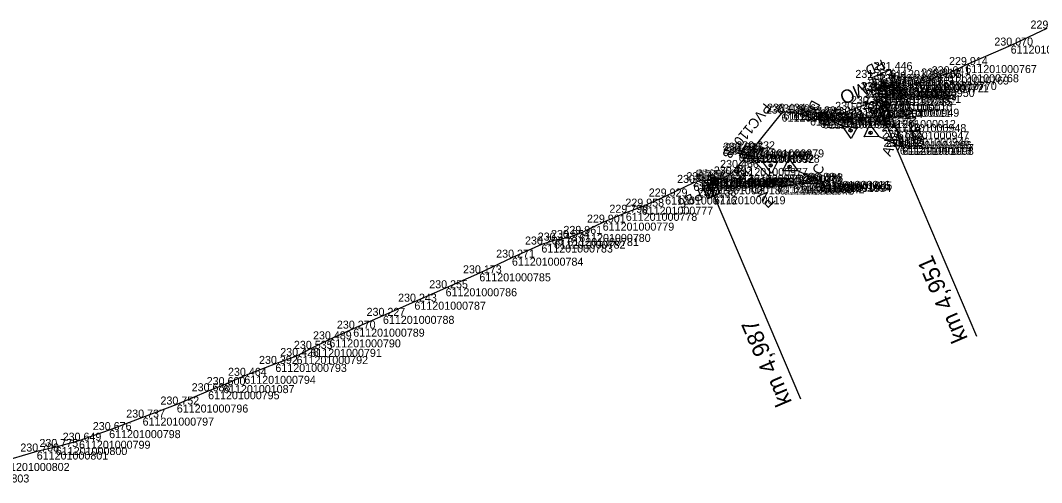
# Model space of a CAD drawing. Extents: x -771040 to -768909, y -1052366 to -1050115.
# Drawn here: x -770450.8 to -770297.8, y -1050286.7 to -1050217.5 of the extents above; entities that cross this region are included whole.
import ezdxf

# ---------------------------------------------------------------- set-up
doc = ezdxf.new("R2010")
doc.units = 0
for name, color, linetype in [('Vrstva 23', 7, 'Continuous'), ('Vrstva 27', 7, 'Continuous'), ('Vrstva 28', 7, 'Continuous'), ('Vrstva 3', 7, 'Continuous'), ('Vrstva 35', 7, 'Continuous'), ('Vrstva 4', 7, 'Continuous'), ('Vrstva 60', 7, 'Continuous'), ('Vrstva 61', 7, 'Continuous')]:
    doc.layers.add(name, color=color, linetype=linetype)

msp = doc.modelspace()

# ---------------------------------------------------------------- linework, layer by layer
at = {"layer": 'Vrstva 23'}
msp.add_lwpolyline([(-770322.43, -1050227.95), (-770319.66, -1050226.75), (-770320.47, -1050224.93), (-770323.23, -1050226.12), (-770322.43, -1050227.95)], dxfattribs=at)
at = {"layer": 'Vrstva 27'}
for p, q in [((-770321.21, -1050227.9), (-770321.22, -1050227.91)), ((-770321.89, -1050229.9), (-770321.85, -1050229.98)), ((-770347.21, -1050241.03), (-770347.17, -1050241.12))]:
    msp.add_line(p, q, dxfattribs=at)
msp.add_lwpolyline([(-770321.21, -1050227.91), (-770323.05, -1050228.7), (-770323.31, -1050228.09), (-770321.48, -1050227.3)], close=True, dxfattribs=at)
msp.add_lwpolyline([(-770321.56, -1050228.79), (-770322.13, -1050228.31), (-770322.17, -1050229.05)], dxfattribs=at)
for centre in [(-770321.87, -1050229.94), (-770347.19, -1050241.08)]:
    msp.add_circle(centre, 0.5, dxfattribs=at)
at = {"layer": 'Vrstva 28'}
for points in [[(-770296.98, -1050218.73), (-770302.4, -1050221.28), (-770309.19, -1050224.19), (-770311.88, -1050225.57), (-770313.36, -1050225.91), (-770315.2, -1050226.73), (-770316.4, -1050227.06), (-770317.15, -1050227.06), (-770318.51, -1050227.77)], [(-770321.45, -1050226.44), (-770322.26, -1050228)], [(-770321.21, -1050228.22), (-770321.27, -1050227.53), (-770321.45, -1050226.44)], [(-770321.21, -1050228.22), (-770321.23, -1050228.95), (-770321.77, -1050229.15)], [(-770320.55, -1050228.68), (-770321.21, -1050228.22)], [(-770318.51, -1050227.77), (-770320.55, -1050228.68)], [(-770321.77, -1050229.15), (-770323.89, -1050230.03), (-770326.25, -1050230.91)], [(-770321.77, -1050229.15), (-770321.87, -1050229.94)], [(-770320.55, -1050228.68), (-770321.23, -1050228.95)], [(-770318.95, -1050235.57), (-770319.23, -1050235.09), (-770319.31, -1050234.14), (-770319.76, -1050233.03), (-770320.82, -1050230.73), (-770321.23, -1050228.95)], [(-770341.08, -1050236.82), (-770336.74, -1050231.46), (-770336.46, -1050231.18)], [(-770336.46, -1050231.18), (-770334.95, -1050231.27), (-770332.47, -1050232.05), (-770330.96, -1050232.4)], [(-770326.25, -1050230.91), (-770327.95, -1050231.6), (-770330.56, -1050232.5)], [(-770321.33, -1050232.43), (-770322.07, -1050230.78), (-770321.87, -1050229.94)], [(-770330.96, -1050232.4), (-770331.13, -1050231.93), (-770331.05, -1050231.58), (-770330.67, -1050231.7)], [(-770330.96, -1050232.4), (-770330.56, -1050232.5)], [(-770318.95, -1050235.57), (-770318.63, -1050236.04), (-770318.64, -1050236.45), (-770319.01, -1050236.41)], [(-770345.53, -1050241.12), (-770344.45, -1050240.58), (-770343.5, -1050239.6), (-770341.74, -1050237.61), (-770341.08, -1050236.82)], [(-770342.55, -1050237.66), (-770343.17, -1050237.46), (-770343.05, -1050237.02), (-770342.73, -1050237.13)], [(-770342.55, -1050237.66), (-770341.74, -1050237.61)], [(-770333.74, -1050241.81), (-770335, -1050242.2), (-770336.54, -1050242.39), (-770337.04, -1050242.37), (-770337.39, -1050242.19), (-770341.74, -1050237.61)], [(-770347.15, -1050241.51), (-770347.2, -1050241.52), (-770348.54, -1050241.44), (-770349.94, -1050241.84), (-770354.19, -1050243.88), (-770357.7, -1050245.4), (-770360.08, -1050246.31), (-770363.54, -1050247.79), (-770367.07, -1050249.48), (-770368.84, -1050250.09), (-770370.83, -1050250.48), (-770372.73, -1050251.07), (-770377.15, -1050253.04), (-770382.03, -1050255.38), (-770387.09, -1050257.62), (-770391.76, -1050259.63), (-770396.48, -1050261.75), (-770400.93, -1050263.67), (-770404.51, -1050265.27), (-770407.36, -1050266.69), (-770409.42, -1050267.77), (-770412.6, -1050268.95), (-770417.25, -1050270.73), (-770420.44, -1050272.12), (-770422.68, -1050273.04), (-770427.37, -1050275.03), (-770432.5, -1050276.99), (-770437.51, -1050278.86), (-770442.03, -1050280.45), (-770445.5, -1050281.39), (-770448.36, -1050282.07), (-770454.15, -1050283.78)], [(-770347.19, -1050241.08), (-770347.58, -1050242.35), (-770346.86, -1050243.84)], [(-770345.53, -1050241.12), (-770346.38, -1050241.24), (-770347.09, -1050241.03), (-770347.19, -1050241.08)], [(-770347.15, -1050241.51), (-770345.53, -1050241.12)], [(-770333.74, -1050241.81), (-770331.65, -1050241.92), (-770330.99, -1050242.01), (-770330.86, -1050241.64), (-770331.18, -1050241.54)]]:
    msp.add_lwpolyline(points, dxfattribs=at)
at = {"layer": 'Vrstva 3'}
for p, q in [((-770322.66, -1050230.82), (-770322.88, -1050231.36)), ((-770322.17, -1050230.61), (-770322.67, -1050231.84)), ((-770321.69, -1050230.4), (-770322.46, -1050232.33)), ((-770321.2, -1050230.19), (-770322.25, -1050232.82)), ((-770320.99, -1050230.68), (-770321.76, -1050232.61)), ((-770320.78, -1050231.17), (-770321.28, -1050232.4)), ((-770321.33, -1050232.43), (-770307.5, -1050264.77)), ((-770320.57, -1050231.66), (-770320.79, -1050232.19)), ((-770347.7, -1050242.03), (-770348.2, -1050243.26)), ((-770347.22, -1050241.82), (-770347.99, -1050243.75)), ((-770346.73, -1050241.61), (-770347.78, -1050244.24)), ((-770348.19, -1050242.24), (-770348.41, -1050242.77)), ((-770346.52, -1050242.1), (-770347.29, -1050244.03)), ((-770346.31, -1050242.59), (-770346.8, -1050243.82)), ((-770346.1, -1050243.07), (-770346.32, -1050243.61)), ((-770346.86, -1050243.84), (-770333.88, -1050274.2))]:
    msp.add_line(p, q, dxfattribs=at)
for points in [[(-770320.41, -1050232.03), (-770322.25, -1050232.82), (-770323.04, -1050230.98), (-770321.2, -1050230.19)], [(-770345.94, -1050243.45), (-770347.78, -1050244.24), (-770348.57, -1050242.4), (-770346.73, -1050241.61)]]:
    msp.add_lwpolyline(points, close=True, dxfattribs=at)
at = {"layer": 'Vrstva 35'}
for points in [[(-770318.95, -1050235.57), (-770319.23, -1050235.09), (-770319.31, -1050234.14), (-770319.76, -1050233.03), (-770320.82, -1050230.73), (-770321.23, -1050228.95)], [(-770341.08, -1050236.82), (-770336.74, -1050231.46), (-770336.46, -1050231.18)], [(-770333.74, -1050241.81), (-770335, -1050242.2), (-770336.54, -1050242.39), (-770337.04, -1050242.37), (-770337.39, -1050242.19), (-770341.74, -1050237.61), (-770342.55, -1050237.66)]]:
    msp.add_lwpolyline(points, dxfattribs=at)
at = {"layer": 'Vrstva 4'}
for p, q in [((-770330.3, -1050231.02), (-770331.04, -1050232.38)), ((-770326.47, -1050233.75), (-770326.33, -1050234.22)), ((-770323.31, -1050234.57), (-770323.47, -1050234.11)), ((-770319.35, -1050237.11), (-770318.67, -1050235.71)), ((-770342.39, -1050236.43), (-770343.08, -1050237.82)), ((-770338.45, -1050238.99), (-770338.29, -1050239.45)), ((-770335.47, -1050239.67), (-770335.62, -1050239.2)), ((-770331.53, -1050242.24), (-770330.84, -1050240.84))]:
    msp.add_line(p, q, dxfattribs=at)
for points in [[(-770330.67, -1050231.7), (-770327.61, -1050233.36), (-770325.38, -1050233.45), (-770326.33, -1050235.21), (-770327.61, -1050233.36)], [(-770319.01, -1050236.41), (-770322.14, -1050234.9), (-770324.38, -1050234.92), (-770323.52, -1050233.12), (-770322.14, -1050234.9)], [(-770342.73, -1050237.13), (-770339.61, -1050238.65), (-770337.37, -1050238.64), (-770338.24, -1050240.44), (-770339.61, -1050238.65)], [(-770331.18, -1050241.54), (-770334.3, -1050240.01), (-770336.54, -1050240.01), (-770335.66, -1050238.21), (-770334.3, -1050240.01)]]:
    msp.add_lwpolyline(points, dxfattribs=at)
for centre in [(-770326.4, -1050233.98), (-770323.39, -1050234.34), (-770338.37, -1050239.22), (-770335.54, -1050239.43)]:
    msp.add_circle(centre, 0.248, dxfattribs=at)
at = {"layer": 'Vrstva 60'}
for p, q in [((-770302.4, -1050221.28), (-770302.4, -1050221.28)), ((-770320.47, -1050224.93), (-770320.47, -1050224.93)), ((-770309.19, -1050224.19), (-770309.19, -1050224.19)), ((-770323.23, -1050226.12), (-770323.23, -1050226.12)), ((-770321.45, -1050226.44), (-770321.45, -1050226.44)), ((-770313.36, -1050225.91), (-770313.36, -1050225.91)), ((-770311.88, -1050225.57), (-770311.88, -1050225.57)), ((-770322.43, -1050227.95), (-770322.43, -1050227.95)), ((-770322.26, -1050228), (-770322.26, -1050228)), ((-770321.27, -1050227.53), (-770321.27, -1050227.53)), ((-770321.21, -1050228.22), (-770321.21, -1050228.22)), ((-770319.66, -1050226.75), (-770319.66, -1050226.75)), ((-770318.51, -1050227.77), (-770318.51, -1050227.77)), ((-770317.15, -1050227.06), (-770317.15, -1050227.06)), ((-770316.4, -1050227.06), (-770316.4, -1050227.06)), ((-770315.2, -1050226.73), (-770315.2, -1050226.73)), ((-770321.77, -1050229.15), (-770321.77, -1050229.15)), ((-770321.23, -1050228.95), (-770321.23, -1050228.95)), ((-770320.55, -1050228.68), (-770320.55, -1050228.68)), ((-770336.46, -1050231.18), (-770336.46, -1050231.18)), ((-770334.95, -1050231.27), (-770334.95, -1050231.27)), ((-770326.25, -1050230.91), (-770326.25, -1050230.91)), ((-770323.89, -1050230.03), (-770323.89, -1050230.03)), ((-770322.07, -1050230.78), (-770322.07, -1050230.78)), ((-770321.87, -1050229.94), (-770321.87, -1050229.94)), ((-770320.82, -1050230.73), (-770320.82, -1050230.73)), ((-770336.74, -1050231.46), (-770336.74, -1050231.46)), ((-770332.47, -1050232.05), (-770332.47, -1050232.05)), ((-770331.13, -1050231.93), (-770331.13, -1050231.93)), ((-770331.05, -1050231.58), (-770331.05, -1050231.58)), ((-770330.96, -1050232.4), (-770330.96, -1050232.4)), ((-770330.67, -1050231.7), (-770330.67, -1050231.7)), ((-770330.56, -1050232.5), (-770330.56, -1050232.5)), ((-770327.95, -1050231.6), (-770327.95, -1050231.6)), ((-770321.33, -1050232.43), (-770321.33, -1050232.43)), ((-770319.76, -1050233.03), (-770319.76, -1050233.03)), ((-770319.31, -1050234.14), (-770319.31, -1050234.14)), ((-770319.23, -1050235.09), (-770319.23, -1050235.09)), ((-770318.95, -1050235.57), (-770318.95, -1050235.57)), ((-770343.05, -1050237.02), (-770343.05, -1050237.02)), ((-770342.73, -1050237.13), (-770342.73, -1050237.13)), ((-770341.08, -1050236.82), (-770341.08, -1050236.82)), ((-770319.01, -1050236.41), (-770319.01, -1050236.41)), ((-770318.64, -1050236.45), (-770318.64, -1050236.45)), ((-770318.63, -1050236.04), (-770318.63, -1050236.04)), ((-770343.17, -1050237.46), (-770343.17, -1050237.46)), ((-770342.55, -1050237.66), (-770342.55, -1050237.66)), ((-770341.74, -1050237.61), (-770341.74, -1050237.61)), ((-770343.5, -1050239.6), (-770343.5, -1050239.6)), ((-770349.94, -1050241.84), (-770349.94, -1050241.84)), ((-770348.54, -1050241.44), (-770348.54, -1050241.44)), ((-770347.2, -1050241.52), (-770347.2, -1050241.52)), ((-770347.19, -1050241.08), (-770347.19, -1050241.08)), ((-770347.15, -1050241.51), (-770347.15, -1050241.51)), ((-770347.09, -1050241.03), (-770347.09, -1050241.03)), ((-770346.38, -1050241.24), (-770346.38, -1050241.24)), ((-770345.53, -1050241.12), (-770345.53, -1050241.12)), ((-770344.45, -1050240.58), (-770344.45, -1050240.58)), ((-770333.74, -1050241.81), (-770333.74, -1050241.81)), ((-770331.65, -1050241.92), (-770331.65, -1050241.92)), ((-770331.18, -1050241.54), (-770331.18, -1050241.54)), ((-770330.99, -1050242.01), (-770330.99, -1050242.01)), ((-770330.86, -1050241.64), (-770330.86, -1050241.64)), ((-770347.58, -1050242.35), (-770347.58, -1050242.35)), ((-770337.39, -1050242.19), (-770337.39, -1050242.19)), ((-770337.04, -1050242.37), (-770337.04, -1050242.37)), ((-770336.54, -1050242.39), (-770336.54, -1050242.39)), ((-770335, -1050242.2), (-770335, -1050242.2)), ((-770354.19, -1050243.88), (-770354.19, -1050243.88)), ((-770346.86, -1050243.84), (-770346.86, -1050243.84)), ((-770360.08, -1050246.31), (-770360.08, -1050246.31)), ((-770357.7, -1050245.4), (-770357.7, -1050245.4)), ((-770363.54, -1050247.79), (-770363.54, -1050247.79)), ((-770367.07, -1050249.48), (-770367.07, -1050249.48)), ((-770372.73, -1050251.07), (-770372.73, -1050251.07)), ((-770370.83, -1050250.48), (-770370.83, -1050250.48)), ((-770368.84, -1050250.09), (-770368.84, -1050250.09)), ((-770377.15, -1050253.04), (-770377.15, -1050253.04)), ((-770382.03, -1050255.38), (-770382.03, -1050255.38)), ((-770387.09, -1050257.62), (-770387.09, -1050257.62)), ((-770391.76, -1050259.63), (-770391.76, -1050259.63)), ((-770396.48, -1050261.75), (-770396.48, -1050261.75)), ((-770400.93, -1050263.67), (-770400.93, -1050263.67)), ((-770404.51, -1050265.27), (-770404.51, -1050265.27)), ((-770409.42, -1050267.77), (-770409.42, -1050267.77)), ((-770407.36, -1050266.69), (-770407.36, -1050266.69)), ((-770412.6, -1050268.95), (-770412.6, -1050268.95)), ((-770417.25, -1050270.73), (-770417.25, -1050270.73)), ((-770420.44, -1050272.12), (-770420.44, -1050272.12)), ((-770422.68, -1050273.04), (-770422.68, -1050273.04)), ((-770427.37, -1050275.03), (-770427.37, -1050275.03)), ((-770432.5, -1050276.99), (-770432.5, -1050276.99)), ((-770437.51, -1050278.86), (-770437.51, -1050278.86)), ((-770445.5, -1050281.39), (-770445.5, -1050281.39)), ((-770442.03, -1050280.45), (-770442.03, -1050280.45)), ((-770448.36, -1050282.07), (-770448.36, -1050282.07))]:
    msp.add_line(p, q, dxfattribs=at)

# ---------------------------------------------------------------- texts
at = {"layer": 'Vrstva 23'}
msp.add_text('RD', height=1.5, rotation=203.4031, dxfattribs=at).set_placement((-770321.69, -1050223.3))
at = {"layer": 'Vrstva 27'}
msp.add_text('MO', height=2, rotation=203.4031, dxfattribs=at).set_placement((-770324.27, -1050226.62))
at = {"layer": 'Vrstva 3'}
for s, height, rotation, p in [('PB7', 1.5, 203.1535, (-770323.4, -1050230.39)), ('PB6', 1.5, 203.1535, (-770348.98, -1050242.86)), ('km 4,951', 2.5, 113.1535, (-770308.78, -1050265.14)), ('km 4,987', 2.5, 113.1535, (-770335.14, -1050274.66))]:
    msp.add_text(s, height=height, rotation=rotation, dxfattribs=at).set_placement(p)
at = {"layer": 'Vrstva 35'}
for s, rotation, p in [('PVC110', 114.7451, (-770315.72, -1050233.92)), ('PVC110', 231.0588, (-770339.33, -1050229.77)), ('PVC 110', 133.5042, (-770337.52, -1050244.71))]:
    msp.add_text(s, height=1.5, rotation=rotation, dxfattribs=at).set_placement(p)
at = {"layer": 'Vrstva 4'}
for s, rotation, p in [('D', 241.5485, (-770332.17, -1050229.31)), ('B', 244.047, (-770345.1, -1050236.53)), ('A', 64.2952, (-770320.46, -1050237.99)), ('C', 63.9012, (-770330.87, -1050240.75))]:
    msp.add_text(s, height=1.5, rotation=rotation, dxfattribs=at).set_placement(p)
at = {"layer": 'Vrstva 60'}
for s, p in [('611201000766', (-770302.4, -1050222.48)), ('611201001155', (-770320.47, -1050226.13)), ('611201000767', (-770309.19, -1050225.39)), ('611201000007', (-770323.23, -1050227.32)), ('611201001158', (-770321.45, -1050227.64)), ('611201000770', (-770315.2, -1050227.93)), ('611201000769', (-770313.36, -1050227.11)), ('611201000768', (-770311.88, -1050226.77)), ('611201000006', (-770322.43, -1050229.15)), ('611201000008', (-770322.26, -1050229.2)), ('611201001102', (-770321.27, -1050228.73)), ('611201000953', (-770321.21, -1050229.42)), ('611201000005', (-770319.66, -1050227.95)), ('611201000950', (-770318.51, -1050228.97)), ('611201000772', (-770317.15, -1050228.26)), ('611201000771', (-770316.4, -1050228.26)), ('611201001065', (-770321.77, -1050230.35)), ('611201000952', (-770321.23, -1050230.15)), ('611201000951', (-770320.55, -1050229.88)), ('611201000981', (-770336.46, -1050232.38)), ('611201000982', (-770334.95, -1050232.47)), ('611201000954', (-770326.25, -1050232.11)), ('611201001064', (-770323.89, -1050231.23)), ('611201000011', (-770322.07, -1050231.98)), ('611201000010', (-770321.87, -1050231.14)), ('611201000949', (-770320.82, -1050231.93)), ('611201000980', (-770336.74, -1050232.66)), ('611201000983', (-770332.47, -1050233.25)), ('611201001100', (-770331.13, -1050233.13)), ('611201001101', (-770331.05, -1050232.78)), ('611201001099', (-770330.96, -1050233.6)), ('611201000014', (-770330.67, -1050232.9)), ('611201000984', (-770330.56, -1050233.7)), ('611201000955', (-770327.95, -1050232.8)), ('611201000012', (-770321.33, -1050233.62)), ('611201000948', (-770319.76, -1050234.23)), ('611201000947', (-770319.31, -1050235.34)), ('611201000946', (-770319.23, -1050236.29)), ('611201001096', (-770318.95, -1050236.77)), ('611201001091', (-770343.17, -1050238.66)), ('611201001090', (-770343.05, -1050238.22)), ('611201000015', (-770342.73, -1050238.33)), ('611201000979', (-770341.08, -1050238.02)), ('611201000013', (-770319.01, -1050237.61)), ('611201001098', (-770318.64, -1050237.65)), ('611201001097', (-770318.63, -1050237.24)), ('611201001092', (-770342.55, -1050238.86)), ('611201000978', (-770341.74, -1050238.81)), ('611201000977', (-770343.5, -1050240.8)), ('611201000775', (-770349.94, -1050243.04)), ('611201000774', (-770348.54, -1050242.64)), ('611201000974', (-770347.2, -1050242.72)), ('611201000017', (-770347.19, -1050242.28)), ('611201000773', (-770347.15, -1050242.71)), ('611201001089', (-770347.09, -1050242.23)), ('611201001088', (-770346.38, -1050242.44)), ('611201000975', (-770345.53, -1050242.32)), ('611201000976', (-770344.45, -1050241.78)), ('611201000941', (-770333.74, -1050243.02)), ('611201001093', (-770331.65, -1050243.12)), ('611201000016', (-770331.18, -1050242.74)), ('611201001094', (-770330.99, -1050243.21)), ('611201001095', (-770330.86, -1050242.84)), ('611201000018', (-770347.58, -1050243.55)), ('611201000945', (-770337.39, -1050243.39)), ('611201000944', (-770337.04, -1050243.57)), ('611201000943', (-770336.54, -1050243.59)), ('611201000942', (-770335, -1050243.4)), ('611201000776', (-770354.19, -1050245.08)), ('611201000019', (-770346.86, -1050245.04)), ('611201000778', (-770360.08, -1050247.52)), ('611201000777', (-770357.7, -1050246.6)), ('611201000779', (-770363.54, -1050248.99)), ('611201000780', (-770367.07, -1050250.68)), ('611201000783', (-770372.73, -1050252.27)), ('611201000782', (-770370.83, -1050251.68)), ('611201000781', (-770368.84, -1050251.29)), ('611201000784', (-770377.15, -1050254.24)), ('611201000785', (-770382.03, -1050256.58)), ('611201000786', (-770387.09, -1050258.82)), ('611201000787', (-770391.76, -1050260.83)), ('611201000788', (-770396.48, -1050262.95)), ('611201000789', (-770400.93, -1050264.87)), ('611201000790', (-770404.51, -1050266.47)), ('611201000792', (-770409.42, -1050268.97)), ('611201000791', (-770407.36, -1050267.89)), ('611201000793', (-770412.6, -1050270.15)), ('611201000794', (-770417.25, -1050271.93)), ('611201001087', (-770420.44, -1050273.32)), ('611201000795', (-770422.68, -1050274.24)), ('611201000796', (-770427.37, -1050276.23)), ('611201000797', (-770432.5, -1050278.19)), ('611201000798', (-770437.51, -1050280.06)), ('611201000800', (-770445.5, -1050282.59)), ('611201000799', (-770442.03, -1050281.65)), ('611201000801', (-770448.36, -1050283.27)), ('611201000802', (-770454.15, -1050284.98)), ('611201000803', (-770460.19, -1050286.7))]:
    msp.add_text(s, height=1.2, dxfattribs=at).set_placement(p)
at = {"layer": 'Vrstva 61'}
for s, p in [('229.866', (-770299.43, -1050218.73)), ('230.070', (-770304.85, -1050221.28)), ('229.914', (-770311.64, -1050224.19)), ('231.474', (-770325.68, -1050226.12)), ('231.446', (-770322.92, -1050224.93)), ('229.910', (-770315.81, -1050225.91)), ('230.041', (-770314.24, -1050225.57)), ('231.488', (-770323.9, -1050226.44)), ('230.134', (-770323.72, -1050227.53)), ('231.502', (-770322.11, -1050226.75)), ('229.816', (-770320.96, -1050227.77)), ('229.780', (-770319.6, -1050227.06)), ('229.967', (-770318.86, -1050227.06)), ('230.097', (-770317.65, -1050226.73)), ('231.530', (-770324.88, -1050227.95)), ('230.608', (-770324.71, -1050228)), ('230.265', (-770324.22, -1050229.15)), ('229.927', (-770323.68, -1050228.95)), ('229.991', (-770323.57, -1050228.22)), ('229.981', (-770322.91, -1050228.68)), ('230.050', (-770328.7, -1050230.91)), ('230.364', (-770326.34, -1050230.03)), ('230.867', (-770324.52, -1050230.78)), ('230.963', (-770324.32, -1050229.94)), ('229.231', (-770323.18, -1050230.73)), ('230.121', (-770339.1, -1050231.46)), ('230.434', (-770338.92, -1050231.18)), ('230.606', (-770337.4, -1050231.27)), ('230.380', (-770334.92, -1050232.05)), ('230.612', (-770333.58, -1050231.93)), ('230.698', (-770333.51, -1050231.58)), ('230.299', (-770333.42, -1050232.4)), ('231.216', (-770333.12, -1050231.7)), ('230.278', (-770333.02, -1050232.5)), ('230.095', (-770330.4, -1050231.6)), ('231.000', (-770323.78, -1050232.43)), ('229.141', (-770322.12, -1050233.03)), ('229.710', (-770321.76, -1050234.14)), ('229.782', (-770321.68, -1050235.09)), ('229.988', (-770321.41, -1050235.57)), ('230.635', (-770345.51, -1050237.02)), ('231.425', (-770345.19, -1050237.13)), ('230.232', (-770343.53, -1050236.82)), ('230.592', (-770321.46, -1050236.41)), ('230.168', (-770321.09, -1050236.04)), ('230.139', (-770321.09, -1050236.45)), ('230.529', (-770345.62, -1050237.46)), ('230.532', (-770345, -1050237.66)), ('230.212', (-770344.19, -1050237.61)), ('230.466', (-770345.95, -1050239.6)), ('230.106', (-770351, -1050241.44)), ('230.248', (-770349.66, -1050241.52)), ('231.113', (-770349.64, -1050241.08)), ('230.181', (-770349.5, -1050241.51)), ('230.401', (-770349.45, -1050241.03)), ('230.222', (-770348.83, -1050241.24)), ('230.373', (-770347.99, -1050241.12)), ('230.492', (-770346.9, -1050240.58)), ('230.884', (-770333.63, -1050241.54)), ('230.283', (-770333.31, -1050241.64)), ('230.029', (-770352.39, -1050241.84)), ('231.035', (-770350.03, -1050242.35)), ('230.018', (-770339.85, -1050242.19)), ('229.826', (-770339.49, -1050242.37)), ('229.694', (-770338.99, -1050242.39)), ('229.545', (-770337.46, -1050242.2)), ('229.861', (-770336.1, -1050241.81)), ('230.075', (-770334.11, -1050241.92)), ('229.972', (-770333.44, -1050242.01)), ('229.929', (-770356.64, -1050243.88)), ('231.138', (-770349.31, -1050243.84)), ('229.958', (-770360.15, -1050245.4)), ('229.901', (-770365.9, -1050247.79)), ('229.799', (-770362.54, -1050246.31)), ('230.142', (-770373.28, -1050250.48)), ('230.054', (-770371.29, -1050250.09)), ('229.961', (-770369.43, -1050249.48)), ('230.206', (-770375.19, -1050251.07)), ('230.271', (-770379.51, -1050253.04)), ('230.173', (-770384.48, -1050255.38)), ('230.255', (-770389.54, -1050257.62)), ('230.243', (-770394.21, -1050259.63)), ('230.227', (-770398.93, -1050261.75)), ('230.270', (-770403.38, -1050263.67)), ('230.489', (-770406.96, -1050265.27)), ('230.535', (-770409.82, -1050266.69)), ('230.392', (-770415.05, -1050268.95)), ('230.428', (-770411.87, -1050267.77)), ('230.464', (-770419.7, -1050270.73)), ('230.600', (-770422.89, -1050272.12)), ('230.688', (-770425.14, -1050273.04)), ('230.752', (-770429.82, -1050275.03)), ('230.737', (-770434.95, -1050276.99)), ('230.676', (-770439.96, -1050278.86)), ('230.775', (-770447.96, -1050281.39)), ('230.649', (-770444.48, -1050280.45)), ('230.708', (-770450.82, -1050282.07))]:
    msp.add_text(s, height=1.2, dxfattribs=at).set_placement(p)

doc.saveas('drawing.dxf')
